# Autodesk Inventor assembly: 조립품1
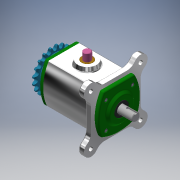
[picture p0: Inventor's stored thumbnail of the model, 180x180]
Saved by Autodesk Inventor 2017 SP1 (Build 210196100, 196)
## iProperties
Part Number: 조립품1
Material: 일반
Document SubType Name: Assembly
Designer: Administrator
Author: Administrator
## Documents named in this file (13)
- C:\Users\Administrator\Desktop\720106V1018\조립품1.iam
- C:\Users\Administrator\Desktop\720106V1018\본체.ipt
- C:\Users\Administrator\Desktop\720106V1018\편심축.ipt
- C:\Users\Administrator\Desktop\720106V1018\커버.ipt
- C:\Users\Administrator\Desktop\720106V1018\베어링 6203.ipt
- C:\Users\Administrator\Desktop\720106V1018\오일 실 17 x 30 x 8.ipt
- C:\Users\Administrator\Desktop\720106V1018\키 5 x 5.ipt
- C:\Users\Administrator\Desktop\720106V1018\스프로킷.ipt
- C:\Users\Administrator\Desktop\720106V1018\부시.ipt
- C:\Users\Administrator\Desktop\720106V1018\슬라이더.ipt
- C:\Users\Administrator\Desktop\720106V1018\볼트 M4 x 12.ipt
- C:\Users\Administrator\Desktop\720106V1018\와셔 4 x 20.ipt
- C:\Users\Administrator\Desktop\720106V1018\육각머리볼트 M4.ipt
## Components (8 placed, 1 different names)
1. M4x0.7x12:1
2. M4x0.7x12:2
3. M4x0.7x12:3
4. M4x0.7x12:4
5. M4x0.7x12:5
6. M4x0.7x12:6
7. M4x0.7x12:7
8. M4x0.7x12:8
